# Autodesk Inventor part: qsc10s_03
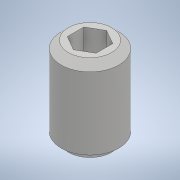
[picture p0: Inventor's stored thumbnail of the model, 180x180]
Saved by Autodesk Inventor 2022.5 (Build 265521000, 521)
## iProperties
Part Number: qsc10s_03
Material: 一般
Document SubType Name: Modeling
Designer: ImaoCorp
Density: 1 g/cm^3
Appearance: 既定
Author: ImaoCorp
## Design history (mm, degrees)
feature "qsc10s_03"
node "ソリッド1"
